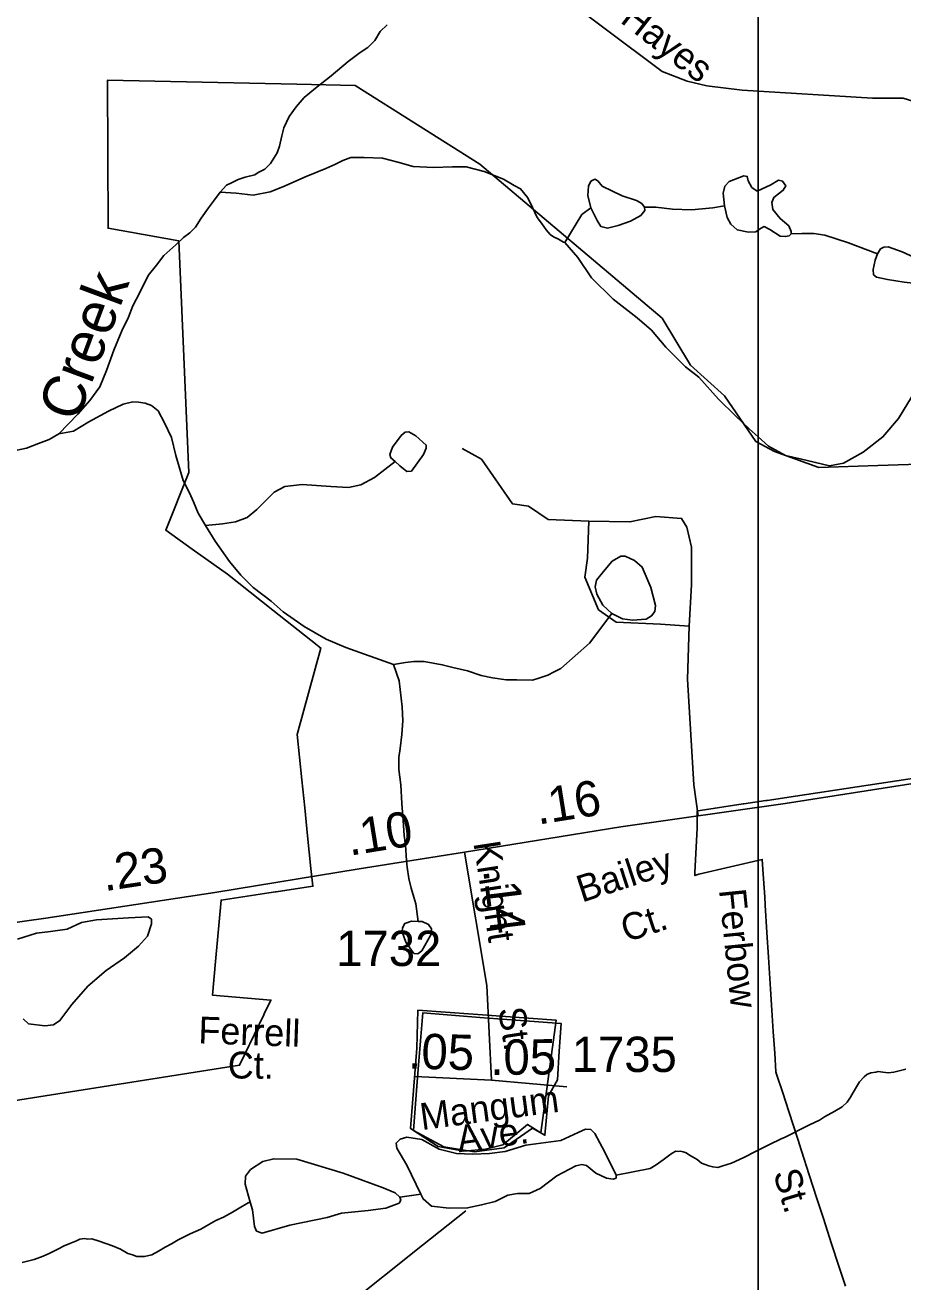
# Model space of a CAD drawing. Extents: x 2056842 to 2160602, y 826753 to 1016856.
# Drawn here: x 2101443 to 2104548, y 862407 to 866853 of the extents above; entities that cross this region are included whole.
import ezdxf

# ---------------------------------------------------------------- set-up
doc = ezdxf.new("R2010")
doc.units = 0
for name, color, linetype in [('Exist Boundary Political City Limit New', 7, 'Continuous'), ('Exist Boundary Political City Limit New Hole', 7, 'Continuous'), ('Exist Hydrographic Creek Single Shore', 7, 'Continuous'), ('Exist Hydrographic Creek Single Shore Label', 7, 'Continuous'), ('Exist Hydrographic Misc Water Feature', 7, 'Continuous'), ('Exist Road Non-System Type 51', 7, 'Continuous'), ('Exist Road Non-System Type 51 Label', 7, 'Continuous'), ('Exist Road Primary NC Attributed', 7, 'Continuous'), ('Exist Road Primary NC Service Mileage Hundredths English Label', 7, 'Continuous'), ('Exist Road Secondary Mileage Hundredths English Label', 7, 'Continuous'), ('Exist Road Secondary Type 51 Attributed', 7, 'Continuous'), ('Exist Road Secondary Type 51 Label', 7, 'Continuous'), ('Exist Road Secondary Type 51 Number Label', 7, 'Continuous'), ('Map Preparation Boundary City Limit Buffer Line', 7, 'Continuous'), ('Map Preparation Inset Cut Line', 7, 'Continuous')]:
    doc.layers.add(name, color=color, linetype=linetype)

msp = doc.modelspace()

# ---------------------------------------------------------------- linework, layer by layer
at = {"layer": 'Exist Boundary Political City Limit New'}
for points in [[(2101357.2, 863040.6), (2102201.5, 863173.7), (2102235.5, 863244.4), (2102238.2, 863250), (2102287.5, 863351.9), (2102289, 863355.2), (2102312.5, 863404.2), (2102106.5, 863421.4), (2102117, 863540.4), (2102136.2, 863757.8), (2102305.5, 863783.4), (2102328.8, 863786.8), (2102331.5, 863787.2), (2102461, 863806.8), (2102454, 863869.9), (2102442.2, 863985), (2102432, 864084.5), (2102422, 864184), (2102405.5, 864344.4), (2102489.2, 864649.6), (2102478.5, 864658.1), (2102475.8, 864660.2), (2102319.8, 864784.1), (2102159.5, 864911.1), (2102034, 865000), (2101940.8, 865066.2), (2102022, 865270.5), (2101986.5, 866090.4), (2101736.8, 866135), (2101734.2, 866658.4), (2102403.8, 866644.6), (2102610.2, 866640.3), (2103051.5, 866361.4), (2103696.5, 865816.6), (2103797, 865649.9), (2103917, 865542), (2104028.2, 865380.1), (2104094, 865344.8), (2104250.8, 865288.9), (2104459, 865295.8), (2105000, 865313.7)], [(2104604, 864191.9), (2104168.2, 864126), (2104068.5, 864110.9), (2104063.8, 864110.2), (2103985.5, 864098.3)], [(2103985.5, 864098.3), (2103983.5, 864098), (2103831, 864074.9), (2103820.8, 864073.4), (2103820, 864012.6), (2103812.5, 863855.8), (2103812.5, 863844.8), (2103826, 863849.6), (2104050.8, 863901.9), (2104055.2, 863833.2), (2104059.2, 863769), (2104061.2, 863739.5), (2104067.2, 863643.7), (2104072.8, 863556), (2104080, 863443.3), (2104084.8, 863368.2), (2104089.5, 863292.6), (2104094.5, 863216.7), (2104098.8, 863150.6), (2104101.5, 863142.1), (2104123, 863075.6), (2104144.2, 863009.8), (2104176, 862911.9), (2104189.2, 862871.4), (2104217, 862785.8), (2104243.8, 862702.8), (2104267, 862631.3), (2104296, 862541.8), (2104320.5, 862466.4), (2104344.5, 862391.8)]]:
    msp.add_lwpolyline(points, dxfattribs=at)
msp.add_lwpolyline([(2103137.5, 862882.1), (2103237.8, 862951.1), (2103281.8, 862926.3), (2103295, 863065), (2103326, 863122.6), (2103332.5, 863223.1), (2103338.8, 863321.8), (2103114.8, 863337.8), (2103051, 863342.6), (2102850, 863359.4), (2102841.5, 863260.6), (2102833, 863159.4), (2102829.2, 863100.1), (2102817.5, 862943), (2102924, 862884.7), (2103033.2, 862867.6)], close=True, dxfattribs=at)
at = {"layer": 'Exist Boundary Political City Limit New Hole'}
msp.add_lwpolyline([(2102832.4, 863368.1), (2103321.7, 863332.9), (2103267.9, 862934.7), (2103219.8, 862964.3), (2103132.6, 862892), (2103071.5, 862877.2), (2102995.5, 862869.8), (2102904.7, 862886.5), (2102806.5, 862949.5), (2102828.7, 863234.7)], close=True, dxfattribs=at)
at = {"layer": 'Exist Hydrographic Creek Single Shore'}
for points in [[(2102133.2, 866263), (2102155.4, 866287.2), (2102173.3, 866295), (2102197.2, 866307.3), (2102221.3, 866315.3), (2102255.2, 866323.5), (2102267.2, 866331.5), (2102291.1, 866343.4), (2102311.2, 866363.7), (2102334.9, 866401.6), (2102343, 866425.7), (2102350.6, 866461.6), (2102358.7, 866489.7), (2102376.6, 866529.7), (2102402.3, 866563.9), (2102430.2, 866597.8), (2102470.2, 866630.1), (2102525.9, 866674.2), (2102585.7, 866724.2), (2102627.7, 866756.5), (2102655.7, 866774.6), (2102679.8, 866798.7), (2102699.5, 866830.8), (2102723.6, 866854.9)], [(2101562.1, 865407.3), (2101629.8, 865477.4), (2101671.8, 865525.8), (2101707.6, 865573.6), (2101731.4, 865631.8), (2101757.2, 865703.8), (2101784.8, 865771.8), (2101808.8, 865819.9), (2101824.7, 865859.9), (2101848.7, 865908), (2101878.4, 865968.1), (2101908.4, 866004.2), (2101934, 866038.4), (2101975.8, 866076.6), (2102003.9, 866102.6), (2102025.9, 866118.6), (2102045.7, 866138.8), (2102065.7, 866170.9), (2102091.7, 866206.8), (2102109.6, 866231), (2102133.2, 866263)], [(2101392.5, 865344.9), (2101448.5, 865356.8), (2101490.2, 865373), (2101528.2, 865387.3), (2101562.1, 865407.3)]]:
    msp.add_lwpolyline(points, dxfattribs=at)
at = {"layer": 'Exist Hydrographic Misc Water Feature'}
for points in [[(2103351.9, 866084.9), (2103347.6, 866085.1), (2103329.9, 866096.7), (2103311.9, 866104.8), (2103300, 866112.7), (2103286.1, 866129), (2103269.7, 866152.6), (2103253.9, 866172.8), (2103237.7, 866208.6), (2103221.3, 866242.7), (2103195.6, 866274.6), (2103173.3, 866286.5), (2103135.4, 866308.5), (2103066.9, 866335.9), (2103003.3, 866352), (2102955.1, 866351.6), (2102887.2, 866349.3), (2102815.3, 866353.4), (2102761.3, 866369.1), (2102707.2, 866383.1), (2102642.8, 866384.7), (2102595.2, 866384.6), (2102567.2, 866374.7), (2102538.9, 866360.3), (2102507.3, 866346.4), (2102437.6, 866318), (2102355.3, 866281.8), (2102309.4, 866263.5), (2102249.7, 866251.5), (2102189.9, 866259.4), (2102133.5, 866263)], [(2103634.3, 866209.8), (2103624.6, 866221.9), (2103606.3, 866232.9), (2103555.3, 866249.9), (2103484.8, 866283.9), (2103469, 866302.2), (2103458.1, 866308.3), (2103444.7, 866301), (2103436.2, 866283.9), (2103433.8, 866251.1), (2103444.7, 866207.3)], [(2104153.3, 866114.9), (2104152.8, 866123.4), (2104144.3, 866142.9), (2104113.9, 866169.6), (2104088.4, 866201.2), (2104084.7, 866225.6), (2104092, 866243.8), (2104124.9, 866269.3), (2104133.4, 866285.2), (2104122.4, 866301), (2104107.8, 866304.6), (2104081.1, 866288.8), (2104032.5, 866265.7), (2104014.2, 866279.1), (2104000.9, 866302.2), (2103997.2, 866318), (2103985.1, 866320.4), (2103934, 866299.7), (2103918.2, 866283.9), (2103912.2, 866258.4), (2103917, 866214.6)], [(2103444.7, 866207.3), (2103411.9, 866183), (2103351.9, 866084.9)], [(2103444.7, 866207.3), (2103466.6, 866162.3), (2103479.9, 866140.4), (2103503, 866135.6), (2103540.7, 866144.1), (2103584.5, 866159.9), (2103620.9, 866179.4), (2103635.5, 866197.6), (2103634.3, 866209.8)], [(2103634.3, 866209.8), (2103674.4, 866209.8), (2103732.8, 866202.5), (2103800.8, 866200), (2103876.2, 866207.3), (2103917, 866214.6)], [(2103917, 866214.6), (2103926.7, 866173.3), (2103938.9, 866148.9), (2103962, 866129.5), (2104002.1, 866121), (2104027.6, 866122.2), (2104044.6, 866134.4), (2104056.8, 866140.4), (2104077.5, 866130.7), (2104113.9, 866106.4), (2104132.1, 866105.2), (2104145.5, 866107.6), (2104153.3, 866114.9)], [(2104153.3, 866114.9), (2104191, 866116.1), (2104233.5, 866116.1), (2104272.4, 866110), (2104355.1, 866083.3), (2104458.4, 866044.4)], [(2104638, 865665.4), (2104595.5, 865564.5), (2104532.3, 865462.3), (2104477.6, 865396.7), (2104407.6, 865342.7), (2104338.3, 865303.7), (2104288.4, 865294), (2104185.1, 865319.5), (2104133.1, 865330.5), (2104072.2, 865363.5), (2104035.7, 865397.4), (2104004, 865425), (2103956, 865471.2), (2103895.7, 865530.7), (2103826.8, 865607.8), (2103779.4, 865644.4), (2103709.1, 865714.3), (2103658.6, 865773.9), (2103608.6, 865818), (2103522.7, 865883.8), (2103446.6, 865959.5), (2103398.2, 866031.2), (2103351.9, 866084.9)], [(2104458.4, 866044.4), (2104469.3, 866061.4), (2104480.2, 866067.5), (2104496, 866068.7), (2104545.9, 866051.7), (2104620, 866017.6), (2104635.8, 865996.9), (2104639.5, 865967.7), (2104633.4, 865942.2), (2104617.6, 865937.3), (2104552, 865944.6), (2104493.6, 865953.1), (2104454.7, 865961.7), (2104443.8, 865970.2), (2104442.6, 865988.4), (2104449.9, 866021.3), (2104458.4, 866044.4)], [(2102081.4, 865083.3), (2102055.1, 865127), (2102039.3, 865166.7), (2102024.6, 865199), (2102002.6, 865242.9), (2101976.6, 865330.9), (2101960.4, 865394.6), (2101936.2, 865446.5), (2101913.9, 865488.4), (2101889.7, 865508.3), (2101868.1, 865516.5), (2101843.9, 865520.1), (2101823.6, 865520.4), (2101790, 865512.1), (2101737.9, 865487.9), (2101668.2, 865449.8), (2101614.5, 865417.4), (2101562.2, 865407.5)], [(2102752.3, 865309.1), (2102736.6, 865322.5), (2102732.9, 865334.6), (2102742.7, 865360.2), (2102773, 865401.5), (2102787.6, 865413.7), (2102801, 865414.9), (2102825.3, 865400.3), (2102861.8, 865367.5), (2102861.8, 865356.5), (2102852.1, 865334.6), (2102809.5, 865275), (2102793.7, 865273.8), (2102768.2, 865294.5), (2102752.3, 865309.1)], [(2102752.3, 865309.1), (2102679.5, 865253.1), (2102630.8, 865227.6), (2102587.1, 865217.9), (2102525.1, 865221.5), (2102423, 865228.8), (2102361.5, 865221.5), (2102323.8, 865200.9), (2102263.1, 865139.8), (2102229, 865111.7), (2102187.2, 865095.7), (2102141.1, 865089.2), (2102081.4, 865083.3)], [(2102746.2, 864591.8), (2102577.1, 864651.4), (2102507.8, 864680.6), (2102430.4, 864726.1), (2102394.5, 864750.2), (2102356.2, 864777.9), (2102313.9, 864816), (2102249.7, 864863.9), (2102206.1, 864907.3), (2102165.5, 864955.3), (2102115.4, 865027.4), (2102081.4, 865083.3)], [(2103517.9, 864771.8), (2103486.3, 864801), (2103465.6, 864839.9), (2103459.5, 864866.7), (2103464.4, 864889.8), (2103488.7, 864920.2), (2103519.1, 864956.7), (2103550.7, 864974.9), (2103565.3, 864974.9), (2103598.1, 864959.1), (2103626, 864936), (2103656.4, 864864.2), (2103673.4, 864799.8), (2103671, 864779.1), (2103658.9, 864763.3), (2103639.4, 864752.3), (2103592, 864748.7), (2103556.8, 864753.6), (2103517.9, 864771.8)], [(2103517.9, 864771.8), (2103438.9, 864667.2), (2103338.4, 864577.9), (2103314.4, 864565.8), (2103292.2, 864553.7), (2103260.4, 864543.5), (2103238.3, 864535.5), (2103182.5, 864537.4), (2103144.2, 864537.2), (2103096.2, 864544.8), (2103056.4, 864552.9), (2103008.4, 864568.7), (2102956.3, 864580.7), (2102918.6, 864590.4), (2102886.4, 864596.5), (2102854.2, 864602.2), (2102818.5, 864602.3), (2102788.4, 864598), (2102746.2, 864591.8)], [(2102833.4, 863681.9), (2102824.9, 863744.4), (2102818.5, 863768.5), (2102809.1, 863800.4), (2102800.7, 863834.1), (2102794.6, 863874), (2102792.3, 863898.3), (2102788.4, 863952), (2102783.9, 863986.3), (2102780.2, 864040.1), (2102775.7, 864100), (2102771.8, 864166), (2102765.4, 864220), (2102765.2, 864262.2), (2102769.3, 864294.1), (2102775.1, 864343.9), (2102778.8, 864392), (2102776.9, 864441.9), (2102766.7, 864533.9), (2102746.2, 864591.8)], [(2101416.7, 863619.4), (2101483.8, 863640.9), (2101533.2, 863647.3), (2101591.5, 863654.9), (2101642.1, 863678.9), (2101695.3, 863687.8), (2101809.2, 863695.4), (2101878.9, 863699.2), (2101890.3, 863690.3), (2101890.3, 863673.9), (2101876.4, 863630.8), (2101844.7, 863595.3), (2101794.1, 863553.5), (2101729.5, 863509.2), (2101664.9, 863453.4), (2101607.9, 863388.8), (2101566.1, 863331.8), (2101543.4, 863316.6), (2101513, 863312.8), (2101454.7, 863320.4), (2101435.7, 863338.1)], [(2102833.4, 863681.9), (2102809.3, 863683.2), (2102786.5, 863675.6), (2102777.6, 863660.4), (2102776.4, 863645.2), (2102790.3, 863609.7), (2102818.2, 863569.2), (2102832.1, 863567.9), (2102846, 863578), (2102877.7, 863635.1), (2102880.2, 863656.6), (2102870.1, 863671.8), (2102847.3, 863681.9), (2102833.4, 863681.9)], [(2104558.6, 863160), (2104516.4, 863149.7), (2104496.5, 863147.5), (2104476.6, 863149.6), (2104460.2, 863151.4), (2104452.6, 863149.2), (2104434.6, 863147.5), (2104420.8, 863141.4), (2104410.6, 863133.3), (2104394.8, 863115.4), (2104384.5, 863097), (2104372.6, 863077.3), (2104362.8, 863061), (2104350.9, 863043.3), (2104332.9, 863027), (2104306.8, 863011), (2104271.1, 862990.9), (2104253.1, 862979), (2104217.2, 862962.5), (2104129.4, 862918.6), (2104119.4, 862914.4), (2104073.3, 862892.2), (2104029.2, 862870.1), (2103985.7, 862847.9), (2103941.4, 862827.8), (2103911.7, 862817.7), (2103893.8, 862811.9), (2103875.4, 862813.9), (2103861.6, 862817.6), (2103835.6, 862827.6), (2103819.8, 862839.8), (2103803.6, 862849.5), (2103793.6, 862855.5), (2103781.3, 862863.5), (2103771.2, 862867.4), (2103761.4, 862869.3), (2103751.1, 862869.2), (2103745.2, 862869.3), (2103731.4, 862863.3), (2103719.5, 862853.3), (2103699.5, 862839.3), (2103691.7, 862833.2), (2103675.7, 862821), (2103653.5, 862808.9), (2103533.8, 862784.6)], [(2102842.4, 862717.5), (2102793.1, 862820.1), (2102757.6, 862880.9), (2102755.1, 862898.6), (2102770.3, 862912.6), (2102793.1, 862918.9), (2102846.2, 862911.3), (2102908.3, 862877.1), (2102969.1, 862861.9), (2103026, 862859.4), (2103085.5, 862861.9), (2103141.3, 862868.2), (2103214.7, 862891), (2103337.5, 862907.5), (2103399.6, 862935.4), (2103424.9, 862948.1), (2103443.9, 862946.8), (2103457.8, 862932.8), (2103493.2, 862865.7), (2103533.8, 862784.6)], [(2102239.5, 862689.5), (2102221.4, 862752.9), (2102222.7, 862780.8), (2102240.4, 862804.9), (2102283.4, 862832.8), (2102322.7, 862842.9), (2102403.7, 862841.6), (2102568.3, 862792.2), (2102710.1, 862740.3), (2102751.9, 862722.5), (2102768.4, 862707.3)], [(2103533.8, 862784.6), (2103533.8, 862774.5), (2103523.6, 862770.7), (2103499.6, 862774.5), (2103461.6, 862792.2), (2103428.7, 862818.8), (2103412.2, 862822.6), (2103390.7, 862817.6), (2103323.6, 862782.1), (2103265.3, 862737.7), (2103226.1, 862720), (2103184.3, 862720), (2103150.1, 862713.7), (2103105.8, 862692.1), (2103057.7, 862679.5), (2103008.3, 862669.3), (2102942.5, 862668.1), (2102880.4, 862675.7), (2102851.3, 862701), (2102842.4, 862717.5)], [(2102239.5, 862689.5), (2102232.3, 862686.7), (2102200.3, 862668.5), (2102176.3, 862654.6), (2102144.3, 862636.3), (2102118.1, 862624.5), (2102092.9, 862610), (2102064.6, 862594), (2102026.6, 862577.8), (2101984.8, 862555.8), (2101960.8, 862542), (2101938.9, 862530), (2101914.9, 862515.7), (2101891.1, 862503.5), (2101865.1, 862497.7), (2101838.6, 862497.7), (2101822.6, 862503.3), (2101806.8, 862507.3), (2101781, 862523.4), (2101752.7, 862535.4), (2101728.9, 862543.1), (2101704.9, 862551.2), (2101678.9, 862559.2), (2101664.9, 862558.9), (2101652.8, 862560.7), (2101636.8, 862558.7), (2101624.7, 862552.7), (2101600.9, 862543), (2101581.1, 862534.7), (2101558.9, 862522.6), (2101530.8, 862508.5), (2101507, 862498.4), (2101475.3, 862486.6), (2101433.2, 862476.3)], [(2102768.4, 862707.3), (2102772.2, 862695.9), (2102765.8, 862685.8), (2102719, 862668.1), (2102656.9, 862660.5), (2102562, 862650.3), (2102511.3, 862635.1), (2102379.7, 862608.5), (2102282.2, 862579.4), (2102261.9, 862587), (2102254.3, 862603.5), (2102248, 862661.7), (2102239.5, 862689.5)], [(2102768.4, 862707.3), (2102842.4, 862717.5)]]:
    msp.add_lwpolyline(points, dxfattribs=at)
at = {"layer": 'Exist Road Non-System Type 51'}
for points in [[(2103437.1, 865098), (2103293.8, 865104.3), (2103223.2, 865152.1), (2103167.1, 865160.4), (2103057.1, 865318.3), (2102988.5, 865355.8)], [(2103792.3, 864726.7), (2103690.5, 864734.3), (2103533.7, 864741.4), (2103471.7, 864785.2), (2103422.6, 864900.6), (2103433, 864967.1), (2103437.1, 865098)], [(2103792.3, 864726.7), (2103800.6, 864873.6), (2103800.6, 865006.6), (2103784, 865077.2), (2103765.3, 865108.4), (2103673.9, 865114.7), (2103582.5, 865096), (2103437.1, 865098)], [(2103824.3, 864055.9), (2103808.9, 864165.5), (2103786.1, 864539.6), (2103792.3, 864726.7)], [(2102072.3, 861999.5), (2102091.6, 861975.8), (2102106.2, 861967.9), (2102115.9, 861969.8), (2102145.3, 861980.9), (2102460.1, 862228.1), (2102573.5, 862317.4), (2102848.3, 862537.2), (2103002.4, 862658.9)]]:
    msp.add_lwpolyline(points, dxfattribs=at)
at = {"layer": 'Exist Road Primary NC Attributed'}
for points in [[(2102996.9, 863927.9), (2103550.1, 864016.7), (2104131.7, 864099.8), (2104938.5, 864225.6), (2105181.5, 864298.3), (2105453.6, 864429.3), (2105729.8, 864599.7), (2105876.5, 864701)], [(2101280.1, 863661.3), (2101516.8, 863694.6), (2102113.9, 863785), (2102624.9, 863868.1), (2102996.9, 863927.9)]]:
    msp.add_lwpolyline(points, dxfattribs=at)
at = {"layer": 'Exist Road Secondary Type 51 Attributed'}
for p, q in [((2103093.3, 863121.3), (2102821.9, 863133.4)), ((2103359.8, 863097.3), (2103093.3, 863121.3))]:
    msp.add_line(p, q, dxfattribs=at)
for points in [[(2105876.5, 864701), (2105873.2, 864871.7), (2105867.5, 865040), (2105848.5, 865157.9), (2105803.3, 865277.2), (2105780.5, 865327.6), (2105740.6, 865388.4), (2105418.1, 865797.7), (2105087.9, 866225.1), (2104923.6, 866414.2), (2104778.7, 866515.5), (2104659, 866561.1), (2104548.7, 866594.4), (2104440.4, 866594.4), (2103979.2, 866623.4), (2103854.7, 866638.6), (2103785.3, 866655.7), (2103696, 866689), (2103284.2, 866999.4), (2102968.7, 867253.6)], [(2102996.9, 863927.9), (2103076.4, 863455.4), (2103093.3, 863121.3)]]:
    msp.add_lwpolyline(points, dxfattribs=at)
at = {"layer": 'Map Preparation Boundary City Limit Buffer Line'}
for points in [[(2101357.2, 863040.6), (2102201.5, 863173.7), (2102235.5, 863244.4), (2102238.2, 863250), (2102287.5, 863351.9), (2102289, 863355.2), (2102312.5, 863404.2), (2102106.5, 863421.4), (2102117, 863540.4), (2102136.2, 863757.8), (2102305.5, 863783.4), (2102328.8, 863786.8), (2102331.5, 863787.2), (2102461, 863806.8), (2102454, 863869.9), (2102442.2, 863985), (2102432, 864084.5), (2102422, 864184), (2102405.5, 864344.4), (2102489.2, 864649.6), (2102478.5, 864658.1), (2102475.8, 864660.2), (2102319.8, 864784.1), (2102159.5, 864911.1), (2102034, 865000), (2101940.8, 865066.2), (2102022, 865270.5), (2101986.5, 866090.4), (2101736.8, 866135), (2101734.2, 866658.4), (2102403.8, 866644.6), (2102610.2, 866640.3), (2103051.5, 866361.4), (2103696.5, 865816.6), (2103797, 865649.9), (2103917, 865542), (2104028.2, 865380.1), (2104094, 865344.8), (2104250.8, 865288.9), (2104459, 865295.8), (2105000, 865313.7)], [(2104604, 864191.9), (2104168.2, 864126), (2104068.5, 864110.9), (2104063.8, 864110.2), (2103985.5, 864098.3)], [(2103985.5, 864098.3), (2103983.5, 864098), (2103831, 864074.9), (2103820.8, 864073.4), (2103820, 864012.6), (2103812.5, 863855.8), (2103812.5, 863844.8), (2103826, 863849.6), (2104050.8, 863901.9), (2104055.2, 863833.2), (2104059.2, 863769), (2104061.2, 863739.5), (2104067.2, 863643.7), (2104072.8, 863556), (2104080, 863443.3), (2104084.8, 863368.2), (2104089.5, 863292.6), (2104094.5, 863216.7), (2104098.8, 863150.6), (2104101.5, 863142.1), (2104123, 863075.6), (2104144.2, 863009.8), (2104176, 862911.9), (2104189.2, 862871.4), (2104217, 862785.8), (2104243.8, 862702.8), (2104267, 862631.3), (2104296, 862541.8), (2104320.5, 862466.4), (2104344.5, 862391.8)]]:
    msp.add_lwpolyline(points, dxfattribs=at)
msp.add_lwpolyline([(2103137.5, 862882.1), (2103237.8, 862951.1), (2103281.8, 862926.3), (2103295, 863065), (2103326, 863122.6), (2103332.5, 863223.1), (2103338.8, 863321.8), (2103114.8, 863337.8), (2103051, 863342.6), (2102850, 863359.4), (2102841.5, 863260.6), (2102833, 863159.4), (2102829.2, 863100.1), (2102817.5, 862943), (2102924, 862884.7), (2103033.2, 862867.6)], close=True, dxfattribs=at)
at = {"layer": 'Map Preparation Inset Cut Line'}
msp.add_lwpolyline([(2059276.8, 845851.8), (2104036.2, 845851.8), (2104036.2, 868310.8), (2085975.1, 868308.6), (2085982, 877260.1), (2059276.8, 877260.1), (2059276.8, 845851.8)], dxfattribs=at)

# ---------------------------------------------------------------- texts
at = {"layer": 'Exist Hydrographic Creek Single Shore Label'}
msp.add_text('Creek', height=150, rotation=69.5469, dxfattribs=at).set_placement((2101626.5, 865443.8))
at = {"layer": 'Exist Road Non-System Type 51 Label'}
for s, rotation, p in [('Bailey', 18.0071, (2103412.8, 863748.8)), ('Ferbow', 275.7886, (2103897.5, 863794.2)), ('Ct.', 18.0071, (2103569.1, 863608.2)), ('Ferrell', 357.9808, (2102054.9, 863251.3)), ('Ct.', 359.4406, (2102159.7, 863127.3)), ('St.', 286.6877, (2104088.6, 862792.3))]:
    msp.add_text(s, height=95, rotation=rotation, dxfattribs=at).set_placement(p)
at = {"layer": 'Exist Road Primary NC Service Mileage Hundredths English Label'}
for s, rotation, p in [('.16', 9.1241, (2103257.5, 864024.7)), ('.10', 9.1922, (2102591.2, 863914.8)), ('.23', 8.6097, (2101723.9, 863789.1))]:
    msp.add_text(s, height=125, rotation=rotation, dxfattribs=at).set_placement(p)
at = {"layer": 'Exist Road Secondary Mileage Hundredths English Label'}
for s, rotation, p in [('.14', 277.0175, (2103062.9, 863864.6)), ('.05', 358.4867, (2102797.3, 863162.1)), ('.05', 0.4355, (2103089.3, 863139.6))]:
    msp.add_text(s, height=125, rotation=rotation, dxfattribs=at).set_placement(p)
at = {"layer": 'Exist Road Secondary Type 51 Label'}
for s, rotation, p in [('Moss - Hayes', 322.1621, (2103215.5, 867120.9)), ('Knight', 278.793, (2103028.5, 863960.4)), ('St.', 278.793, (2103116.2, 863372.9)), ('Mangum', 7.6036, (2102846.2, 862944.1)), ('Ave.', 7.6842, (2102977.1, 862865.4))]:
    msp.add_text(s, height=95, rotation=rotation, dxfattribs=at).set_placement(p)
at = {"layer": 'Exist Road Secondary Type 51 Number Label'}
for s, p in [('1732', (2102543.5, 863524.8)), ('1735', (2103376.6, 863149.9))]:
    msp.add_text(s, height=125, dxfattribs=at).set_placement(p)

doc.saveas('drawing.dxf')
